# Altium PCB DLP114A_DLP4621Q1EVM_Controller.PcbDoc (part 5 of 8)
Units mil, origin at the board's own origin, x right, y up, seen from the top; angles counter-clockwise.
Board outline 4803.15 x 2598.43 mil, 14 copper layers (Top Layer, GND 1, SIGNAL 1, GND 2, SIGNAL 2, PWR SPLIT PLANE 1, GND 3, GND 4, PWR SPLIT PLANE 2, SIGNAL 3, GND 5, SIGNAL 4, GND 6, Bottom Layer), stack 91.4 mil thick; 489 components, 394 nets, 1925 pads, 1273 vias.
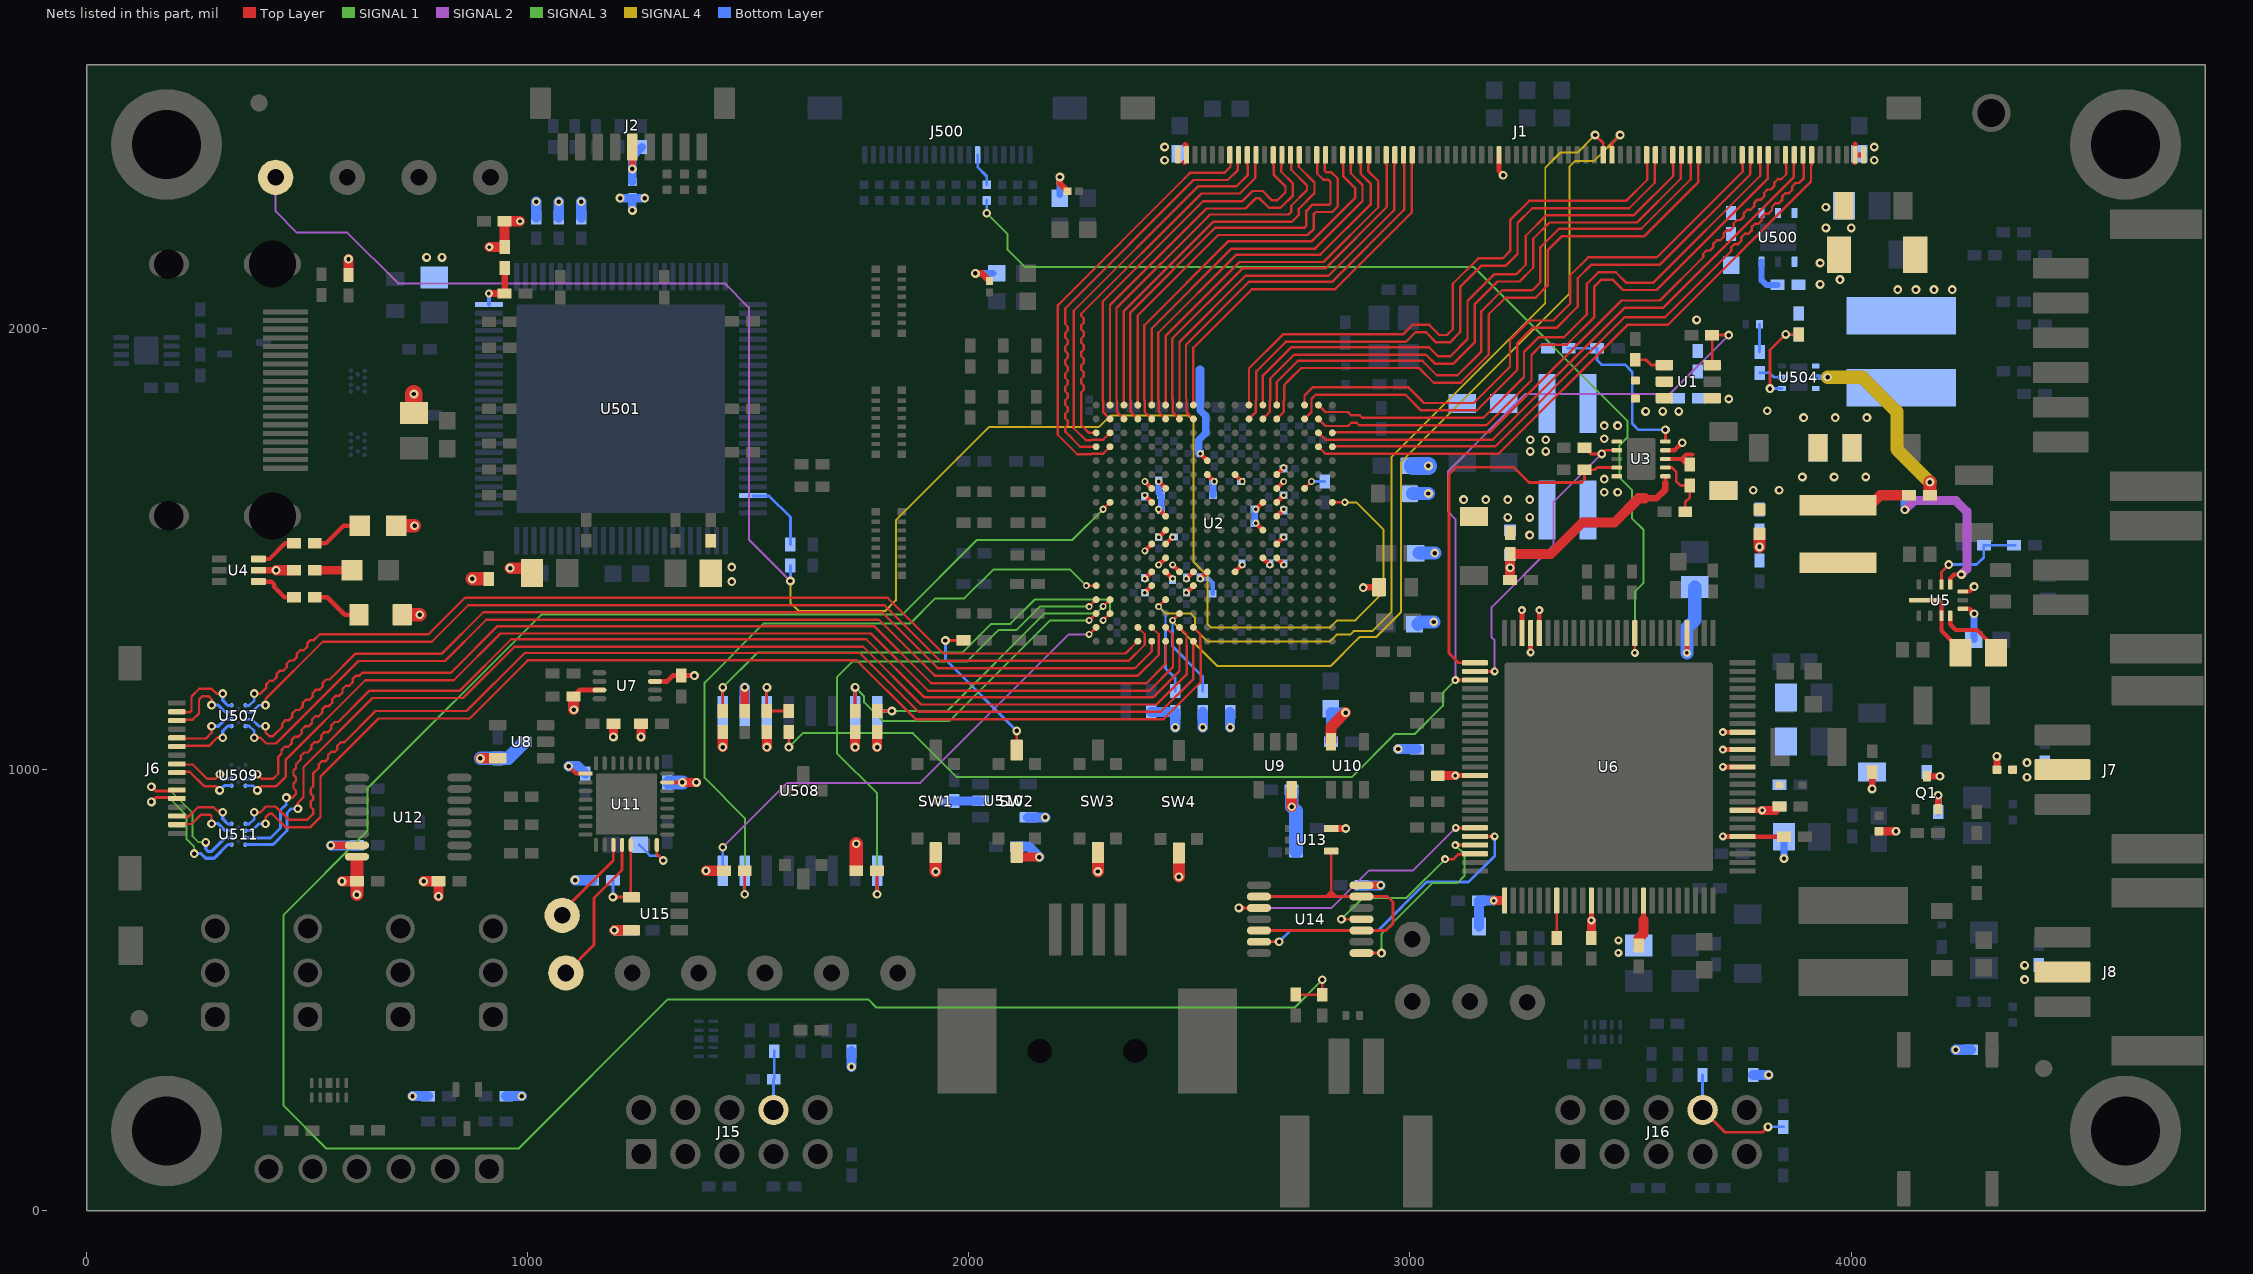
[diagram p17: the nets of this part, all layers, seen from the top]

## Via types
v1: diameter 20, hole 10, Top Layer to Bottom Layer, tented top, 716 vias
v2: diameter 16, hole 8, Top Layer to Bottom Layer, 234 vias
v3: diameter 19.68, hole 7.87, Top Layer to Bottom Layer, 170 vias
v4: diameter 18, hole 8, Top Layer to Bottom Layer, tented top, 78 vias
v5: diameter 18, hole 8, Top Layer to Bottom Layer, tented bottom, 51 vias
v6: diameter 39.37, hole 19.68, Top Layer to Bottom Layer, 24 vias

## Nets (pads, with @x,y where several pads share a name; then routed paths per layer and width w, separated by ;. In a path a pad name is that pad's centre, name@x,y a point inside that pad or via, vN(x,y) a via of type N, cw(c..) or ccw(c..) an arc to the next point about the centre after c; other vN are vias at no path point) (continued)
HS_A_WDATA1_N: J1.26 U2.A12 | length 1340.7
  Top Layer w5.4: U2.A12@2635.03,1826.6 2635.03,1910.14 2711.8,1986.91 2983.97,1986.91 3005.4,2008.35 3043.5,2008.35 3066.32,1985.53 3083.83,1985.53 3096.88,1998.58 3096.88,2101.45 3154.99,2159.57 3210.65,2159.57 3227.04,2175.96 3227.04,2246.25 3270.25,2289.46 3490.06,2289.46 3537.98,2337.37 3537.98,2369.87 3536.54,2371.32 J1.26@3536.54,2393.7
HS_A_WDATA1_P: J1.25 U2.B12 | length 1379.2
  Top Layer w5.4: U2.B12@2635.03,1795.11 2650.78,1810.86 2650.78,1836.47 2651.83,1837.52 2651.83,1903.18 2718.76,1970.11 2990.92,1970.11 3012.36,1991.55 3036.54,1991.55 3059.36,1968.73 3090.78,1968.73 3113.68,1991.63 3113.68,2094.49 3161.95,2142.77 3217.61,2142.77 3243.84,2169.01 3243.84,2239.29 3277.21,2272.66 3497.02,2272.66 3554.78,2330.41 3554.78,2369.87 3556.22,2371.32 J1.25@3556.22,2393.7
HS_A_WDATA2_N: J1.23 U2.A13 | length 1338.5
  Top Layer w5.4: U2.A13@2666.53,1826.6 2666.53,1893.63 2730.36,1957.46 3043.3,1957.46 3048.22,1952.54 3063.44,1937.32 3091.52,1937.32 3130.4,1976.2 3130.4,2062.38 3191.49,2123.46 3241.13,2123.46 3262.46,2144.79 3262.46,2210.53 3309.15,2257.22 3507.66,2257.22 3597.03,2346.59 3597.03,2369.87 3595.59,2371.32 J1.23@3595.59,2393.7
HS_A_WDATA2_P: J1.22 U2.B13 | length 1377
  Top Layer w5.4: U2.B13@2666.53,1795.11 2682.27,1810.86 2682.27,1836.47 2683.33,1837.52 2683.33,1886.67 2737.32,1940.66 3036.34,1940.66 3056.48,1920.52 3098.47,1920.52 3147.2,1969.25 3147.2,2055.42 3198.45,2106.66 3248.09,2106.66 3279.26,2137.83 3279.26,2203.57 3316.1,2240.42 3514.62,2240.42 3613.83,2339.63 3613.83,2369.87 3615.28,2371.32 J1.22@3615.28,2393.7
HS_A_WDATA3_N: J1.21 U2.A14 | length 1364.5
  Top Layer w5.4: U2.A14@2698.02,1826.6 2698.02,1878.84 2746.53,1927.35 3027.6,1927.35 3032.52,1922.43 3060.81,1894.15 3107.81,1894.15 3161.83,1948.16 3161.83,2039.37 3209.32,2086.86 3277.82,2086.86 3295.3,2104.34 3295.3,2183.97 3337.71,2226.38 3524.42,2226.38 3636.4,2338.37 3636.4,2369.87 3634.96,2371.32 J1.21@3634.96,2393.7
HS_A_WDATA3_P: J1.20 U2.B14 | length 1402.9
  Top Layer w5.4: U2.B14@2698.02,1795.11 2713.77,1810.86 2713.77,1836.47 2714.82,1837.52 2714.82,1871.88 2724.91,1881.97 2753.49,1910.55 3020.64,1910.55 3053.85,1877.35 3114.77,1877.35 3178.63,1941.2 3178.63,2032.41 3216.28,2070.06 3284.78,2070.06 3312.1,2097.38 3312.1,2177.01 3344.67,2209.58 3531.38,2209.58 3653.2,2331.41 3653.2,2369.87 3654.65,2371.32 J1.20@3654.65,2393.7
HS_A_WDATA4_N: J1.15 U2.A16 | length 1366.1
  Top Layer w5.4: U2.A16@2761.01,1826.6 2761.01,1848.67 2779.07,1866.72 2996.65,1866.72 3032.13,1831.24 3144.47,1831.24 3226.74,1913.51 3226.74,1973.93 3271.11,2018.3 3324.92,2018.3 3363.49,2056.87 3363.49,2120.95 3404.35,2161.81 3559.91,2161.81 3754.51,2356.42 3754.51,2369.87 3753.07,2371.32 J1.15@3753.07,2393.7
HS_A_WDATA4_P: J1.14 U2.B16 | length 1404.5
  Top Layer w5.4: U2.B16@2761.01,1795.11 2776.76,1810.86 2776.76,1840.66 2786.03,1849.92 2989.69,1849.92 3025.18,1814.44 3151.43,1814.44 3243.54,1906.55 3243.54,1966.98 3278.07,2001.5 3331.88,2001.5 3380.29,2049.91 3380.29,2113.99 3411.31,2145.01 3566.87,2145.01 3771.31,2349.46 3771.31,2369.87 3772.76,2371.32 J1.14@3772.76,2393.7
HS_A_WDATA5_N: J1.13 U2.A17 | length 1381.8
  Top Layer w5.4: U2.A17@2792.51,1826.6 2808.28,1810.83 2859.43,1810.83 2867.02,1803.24 2886.23,1803.24 2891.64,1797.83 3166.43,1797.83 3258.61,1890.01 3258.61,1947.12 3291.5,1980.01 3348.61,1980.01 3400.6,2032.01 3400.6,2101.22 3427.18,2127.8 3466.3,2127.8 3489.76,2104.34 3551.8,2104.34 3793.88,2346.42 3793.88,2369.87 3792.44,2371.32 J1.13@3792.44,2393.7
HS_A_WDATA5_P: J1.12 U2.B17 | length 1409.6
  Top Layer w5.4: U2.B17@2792.51,1795.11 2808.38,1779.24 2859.82,1779.24 2867.02,1786.44 2879.27,1786.44 2884.68,1781.03 3173.38,1781.03 3275.41,1883.05 3275.41,1940.16 3298.46,1963.21 3355.57,1963.21 3417.4,2025.05 3417.4,2094.26 3434.14,2111 3459.34,2111 3482.8,2087.54 3558.76,2087.54 3810.68,2339.46 3810.68,2369.87 3812.13,2371.32 J1.12@3812.13,2393.7
HS_A_WDATA6_N: J1.10 U2.C18 | length 1353.7
  Top Layer w5.4: U2.C18@2824.01,1763.61 2825.06,1764.66 3180.3,1764.66 3479.25,2063.62 3566.86,2063.62 3664.83,2161.58 3664.83,2169.57 3672.36,2177.1 3680.35,2177.1 3687.88,2184.63 3687.88,2192.62 3695.41,2200.15 3703.4,2200.15 3710.93,2207.69 3710.93,2215.68 3718.46,2223.21 3726.45,2223.21 3733.98,2230.74 3733.98,2238.73 3741.52,2246.26 3749.5,2246.26 3757.04,2253.79 3757.04,2261.78 3764.57,2269.31 3772.56,2269.31 3780.09,2276.84 3780.09,2284.83 3787.62,2292.36 3795.61,2292.36 3803.14,2299.9 3803.14,2307.88 3810.67,2315.42 3818.66,2315.42 3826.19,2322.95 3826.19,2330.94 3833.72,2338.47 3841.71,2338.47 3852.94,2349.69 3852.94,2369.87 3851.5,2371.32 J1.10@3851.5,2393.7
HS_A_WDATA6_P: J1.9 U2.C17 | length 1381.7
  Top Layer w5.4: U2.C17@2792.51,1763.61 2808.26,1747.86 3187.26,1747.86 3486.21,2046.82 3573.82,2046.82 3869.74,2342.74 3869.74,2369.87 3871.18,2371.32 J1.9@3871.18,2393.7
HS_A_WDATA7_N: J1.8 U2.D18 | length 1407.1
  Top Layer w5.4: U2.D18@2824.01,1732.12 2825.06,1733.17 3193.68,1733.17 3485.77,2025.26 3492.43,2025.26 3577.54,2025.26 3728.34,2176.06 3728.34,2184.05 3735.87,2191.58 3743.86,2191.58 3751.39,2199.12 3751.39,2207.1 3758.93,2214.64 3766.91,2214.64 3774.45,2222.17 3774.45,2230.16 3781.98,2237.69 3789.97,2237.69 3797.5,2245.22 3797.5,2253.21 3805.03,2260.74 3813.02,2260.74 3820.55,2268.27 3820.55,2276.26 3828.08,2283.79 3836.07,2283.79 3843.6,2291.33 3843.6,2299.31 3851.14,2306.85 3859.12,2306.85 3866.66,2314.38 3866.66,2322.37 3874.19,2329.9 3882.18,2329.9 3892.31,2340.03 3892.31,2369.87 3890.87,2371.32 J1.8@3890.87,2393.7
HS_A_WDATA7_P: J1.7 U2.D17 | length 1439.8
  Top Layer w5.4: U2.D17@2792.51,1732.12 2808.26,1716.37 3200.64,1716.37 3492.73,2008.46 3499.39,2008.46 3584.5,2008.46 3909.11,2333.07 3909.11,2369.87 3910.55,2371.32 J1.7@3910.55,2393.7
HS_B_CLK_N: J1.63 U2.A4 | length 915.2
  Top Layer w5.4: U2.A4@2383.06,1826.6 2383.06,2029.6 2565.51,2212.05 2767.99,2212.05 2782.06,2226.12 2782.06,2259.96 2786.33,2264.23 2823.66,2264.23 2836.67,2277.23 2836.67,2339.58 2822.12,2354.13 2810.55,2354.13 2806.75,2357.93 2806.75,2392.26 J1.63@2808.19,2393.7
HS_B_CLK_P: J1.64 U2.B4 | length 953.7
  Top Layer w5.4: U2.B4@2383.06,1795.11 2367.31,1810.86 2367.31,1836.06 2366.26,1837.11 2366.26,2036.55 2553.63,2223.93 2558.55,2228.85 2761.03,2228.85 2765.26,2233.08 2765.26,2266.92 2779.37,2281.03 2816.71,2281.03 2819.87,2284.19 2819.87,2332.62 2815.17,2337.33 2803.59,2337.33 2789.95,2350.97 2789.95,2392.26 J1.64@2788.5,2393.7
HS_B_WDATA0_N: J1.53 U2.A8 | length 883.1
  Top Layer w5.4: U2.A8@2509.05,1826.6 2509.05,1956.55 2641.61,2089.11 2830.28,2089.11 3003.6,2262.43 3003.6,2369.87 3005.04,2371.32 J1.53@3005.04,2393.7
HS_B_WDATA0_P: J1.54 U2.B8 | length 921.5
  Top Layer w5.4: U2.B8@2509.05,1795.11 2493.3,1810.86 2493.3,1840.97 2492.25,1842.03 2492.25,1963.5 2634.65,2105.91 2823.32,2105.91 2986.8,2269.39 2986.8,2369.87 2985.35,2371.32 J1.54@2985.35,2393.7
HS_B_WDATA1_N: J1.55 U2.A7 | length 879.4
  Top Layer w5.4: U2.A7@2477.55,1826.6 2477.55,1969.96 2627.35,2119.76 2815.31,2119.76 2964.23,2268.67 2964.23,2369.87 2965.67,2371.32 J1.55@2965.67,2393.7
HS_B_WDATA1_P: J1.56 U2.B7 | length 917.8
  Top Layer w5.4: U2.B7@2477.55,1795.11 2461.8,1810.86 2461.8,1840.66 2460.75,1841.71 2460.75,1976.92 2620.39,2136.56 2808.35,2136.56 2947.43,2275.63 2947.43,2369.87 2945.98,2371.32 J1.56@2945.98,2393.7
HS_B_WDATA2_N: J1.58 U2.A6 | length 888.3
  Top Layer w5.4: U2.A6@2446.05,1826.6 2446.05,1983.46 2613.44,2150.85 2803.71,2150.85 2928.1,2275.24 2928.1,2334.37 2905.17,2357.3 2905.17,2369.87 2906.61,2371.32 J1.58@2906.61,2393.7
HS_B_WDATA2_P: J1.59 U2.B6 | length 926.8
  Top Layer w5.4: U2.B6@2446.05,1795.11 2430.31,1810.86 2430.31,1836.47 2429.25,1837.52 2429.25,1990.42 2606.48,2167.65 2796.75,2167.65 2911.3,2282.2 2911.3,2327.41 2888.37,2350.35 2888.37,2369.87 2886.93,2371.32 J1.59@2886.93,2393.7
HS_B_WDATA3_N: J1.60 U2.A5 | length 887.6
  Top Layer w5.4: U2.A5@2414.56,1826.6 2414.56,2000.29 2595.66,2181.39 2784.89,2181.39 2892.49,2288.99 2892.49,2325.3 2865.8,2351.99 2865.8,2369.87 2867.24,2371.32 J1.60@2867.24,2393.7
HS_B_WDATA3_P: J1.61 U2.B5 | length 926
  Top Layer w5.4: U2.B5@2414.56,1795.11 2398.81,1810.86 2398.81,1836.06 2397.76,1837.11 2397.76,2007.25 2588.7,2198.19 2777.93,2198.19 2875.69,2295.95 2875.69,2318.34 2849,2345.03 2849,2369.87 2847.56,2371.32 J1.61@2847.56,2393.7
HS_B_WDATA4_N: J1.66 U2.A3 | length 865.7
  Top Layer w5.4: U2.A3@2351.57,1826.6 2351.57,2039.53 2553.81,2241.78 2731.86,2241.78 2747.69,2257.62 2747.69,2271.38 2783.45,2307.14 2783.45,2331.18 2747.69,2366.94 2747.69,2392.26 J1.66@2749.13,2393.7
HS_B_WDATA4_P: J1.67 U2.B3 | length 904.1
  Top Layer w5.4: U2.B3@2351.57,1795.11 2335.82,1810.86 2335.82,1836.06 2334.77,1837.11 2334.77,2046.49 2541.93,2253.66 2546.85,2258.58 2724.9,2258.58 2730.89,2264.58 2730.89,2278.34 2766.65,2314.1 2766.65,2324.22 2730.89,2359.98 2730.89,2392.26 J1.67@2729.45,2393.7
HS_B_WDATA5_N: J1.68 U2.A2 | length 865.2
  Top Layer w5.4: U2.A2@2320.07,1826.6 2320.07,2053.8 2538.36,2272.09 2627.09,2272.09 2650.1,2295.11 2659.14,2295.11 2680.5,2273.76 2706.2,2273.76 2734.5,2302.06 2734.5,2329.2 2708.32,2355.38 2708.32,2369.87 2709.76,2371.32 J1.68@2709.76,2393.7
HS_B_WDATA5_P: J1.69 U2.B2 | length 903.7
  Top Layer w5.4: U2.B2@2320.07,1795.11 2304.32,1810.86 2304.32,1836.06 2303.27,1837.11 2303.27,2060.76 2531.4,2288.89 2620.13,2288.89 2643.15,2311.91 2666.1,2311.91 2687.46,2290.56 2699.24,2290.56 2717.7,2309.02 2717.7,2322.24 2691.52,2348.42 2691.52,2369.87 2690.08,2371.32 J1.69@2690.08,2393.7
HS_B_WDATA6_N: J1.71 U2.C1 | length 898.3
  Top Layer w5.4: U2.C1@2288.57,1763.61 2272.31,1763.61 2254.75,1781.18 2254.75,1855.69 2260.75,1861.69 2260.75,1870.29 2254.75,1876.29 2254.75,1886.18 2260.75,1892.18 2260.75,1900.78 2254.75,1906.78 2254.75,1916.66 2260.75,1922.66 2260.75,1931.26 2254.75,1937.26 2254.75,1947.15 2260.75,1953.15 2260.75,1961.75 2254.75,1967.75 2254.75,1977.64 2260.75,1983.64 2260.75,1992.23 2254.75,1998.23 2254.75,2008.12 2260.75,2014.12 2260.75,2022.72 2254.75,2028.72 2254.75,2033.58 2527.46,2306.29 2614.24,2306.29 2649.27,2341.31 2649.27,2369.87 2650.71,2371.32 J1.71@2650.71,2393.7
HS_B_WDATA6_P: J1.72 U2.C2 | length 934.8
  Top Layer w5.4: U2.C2@2320.07,1763.61 2304.32,1747.86 2279.12,1747.86 2278.07,1746.81 2265.35,1746.81 2237.95,1774.22 2237.95,1881.97 2237.95,2040.54 2520.5,2323.09 2607.28,2323.09 2632.47,2348.27 2632.47,2369.87 2631.02,2371.32 J1.72@2631.02,2393.7
HS_B_WDATA7_N: J1.73 U2.D1 | length 959.6
  Top Layer w5.4: U2.D1@2288.57,1732.12 2252.67,1732.12 2218.34,1766.45 2218.34,1776.34 2224.34,1782.34 2224.34,1790.94 2218.34,1796.94 2218.34,1806.83 2224.34,1812.83 2224.34,1821.42 2218.34,1827.42 2218.34,1837.31 2224.34,1843.31 2224.34,1851.91 2218.34,1857.91 2218.34,1867.8 2224.34,1873.8 2224.34,1882.39 2218.34,1888.39 2218.34,1898.28 2224.34,1904.28 2224.34,1912.88 2218.34,1918.88 2218.34,1928.77 2224.34,1934.77 2224.34,1943.37 2218.34,1949.37 2218.34,1959.25 2224.34,1965.25 2224.34,1973.85 2218.34,1979.85 2218.34,1989.74 2224.34,1995.74 2224.34,2004.34 2218.34,2010.34 2218.34,2045.72 2509.52,2336.89 2586.96,2336.89 2609.9,2359.83 2609.9,2392.26 J1.73@2611.34,2393.7
HS_B_WDATA7_P: J1.74 U2.D2 | length 986.1
  Top Layer w5.4: U2.D2@2320.07,1732.12 2304.32,1716.37 2279.12,1716.37 2278.07,1715.32 2245.72,1715.32 2201.54,1759.49 2201.54,2052.68 2490.68,2341.81 2502.56,2353.69 2580,2353.69 2593.1,2366.79 2593.1,2392.26 J1.74@2591.65,2393.7
HSEL_PU: R37.2 SW2.1 | length 356.4
  Top Layer w6.3: v1(1946.79,1293.01) R37.2@1987.78,1293.01 ; SW2.1@2108.66,1044.67 v1(2108.66,1088.07)
  Bottom Layer w6.3: v1(1946.79,1293.01) 1946.79,1249.94 v1(2108.66,1088.07)
HSYNC: R539.2 TP1.1 U2.H18 | length 4392.7
  Top Layer w6.3: U2.H18@2824.13,1606.26 v2(2852.49,1606.26)
  SIGNAL 4 w4.5: v1(1595.45,1427.84) 1595.45,1378.39 1614.09,1359.75 1810.45,1359.75 1834.39,1383.69 1834.39,1565.36 2046.22,1777.18 2295.41,1777.18 2321.21,1802.98 2497.12,1802.98 2509.23,1790.88 2509.23,1471.48 2540.59,1440.13 2540.59,1330.56 2548.5,1322.64 2819.5,1322.64 2835.35,1338.5 2876.09,1338.5 2939.78,1402.2 2939.78,1544.89 2878.41,1606.26 v2(2852.49,1606.26)
  SIGNAL 2 w4.5: TP1.1@428.53,2342.8 428.53,2265.59 476.47,2217.65 590.92,2217.65 705.98,2102.58 1446.35,2102.58 1501.38,2047.56 1501.38,1521.9 v1(1595.45,1427.84)
  Bottom Layer w6.3: v1(1595.45,1427.84) R539.2@1595.45,1463.04
HSYNC_S: R539.1 U501.48 | length 167.5
  Bottom Layer w6.3: U501.48@1510.53,1621.47 1511.23,1620.77 1547.3,1620.77 1595.45,1572.62 R539.1@1595.45,1510.28
HUD_LEDSEL_0: U6.20 U14.3 | length 655.7
  Top Layer w6.3: v1(2612.12,686.71) U14.3@2657.68,686.71 ; v4(3103.78,868.12) U6.20@3147.12,868.12
  SIGNAL 2 w4.5: v1(2612.12,686.71) 2822.17,686.71 2907.22,771.76 3007.43,771.76 v4(3103.78,868.12)
HUD_LEDSEL_1: U6.21 U14.6 | length 703.7
  Top Layer w6.3: U14.6@2657.68,609.94 v1(2703.24,609.94) ; U6.21@3147.52,848.84 v4(3192.05,848.84)
  Bottom Layer w6.3: v1(2703.24,609.94) 2729.17,635.87 2928.18,635.87 3037.86,745.55 3132.85,745.55 3192.05,804.74 v4(3192.05,848.84)
HUD_LEDSEL_2: U6.22 U14.8 | length 454.6
  Top Layer w6.3: U14.8@2889.97,584.35 v1(2935.52,584.35) ; v4(3103,829.15) U6.22@3147.52,829.15
  SIGNAL 3 w4.5: v1(2935.52,584.35) 2935.52,628.02 3050.36,742.86 3107.18,742.86 3123.63,759.32 3123.63,808.51 v4(3103,829.15)
HUD_LEDSEL_3: U6.23 U14.11 | length 410.1
  Top Layer w6.3: v1(2844.41,661.12) U14.11@2889.97,661.12 ; v4(3079.8,797.19) 3099,797.19 3110.37,808.56 3146.62,808.56 U6.23@3147.52,809.47
  SIGNAL 3 w4.5: v1(2844.41,661.12) 2892.43,709.15 2991.76,709.15 v4(3079.8,797.19)
JTAGRSTZ: R531.2 U2.G16 | length 52.1
  Top Layer w6.3: U2.G16@2761.01,1637.63 v2(2776.76,1653.38)
  Bottom Layer w6.3: v2(2776.76,1653.38) R531.2@2806.57,1653.38
L1_CLK_N: U2.U6 U509.C4 | length 2449.9
  Top Layer w5.4: v1(387.28,953.13) 397.08,962.92 430.38,962.92 451.19,983.73 451.19,1022.21 631.73,1202.74 832.31,1202.74 938.37,1308.8 1778.09,1308.8 1907.79,1179.11 2409.35,1179.11 2462.85,1232.62 2462.85,1280.7 2461.8,1281.75 2461.8,1306.92 U2.U6@2446.05,1322.67
  Bottom Layer w6.3: U509.C4@360.17,963.82 376.59,963.82 v1(387.28,953.13)
L1_CLK_N_S: J6.9 U509.A4 | length 146.3
  Top Layer w5.4: J6.9@204.72,993.51 206.17,994.96 233.85,994.96 266.08,962.73 291.96,962.73 v1(301.56,953.13)
  Bottom Layer w7: v1(301.56,953.13) 312.25,963.82 U509.A4@328.67,963.82
L1_CLK_P: U2.V6 U509.C3 | length 2421
  Top Layer w5.4: v1(386.78,989.51) 396.57,979.72 423.42,979.72 434.39,990.69 434.39,1029.17 441.73,1036.51 441.73,1044.5 449.27,1052.03 457.25,1052.03 464.79,1059.56 464.79,1067.55 472.32,1075.08 480.31,1075.08 487.84,1082.61 487.84,1090.6 495.37,1098.13 503.36,1098.13 510.89,1105.67 510.89,1113.65 518.42,1121.19 526.41,1121.19 533.94,1128.72 533.94,1136.71 541.47,1144.24 549.46,1144.24 557,1151.77 557,1159.76 564.53,1167.29 572.52,1167.29 580.05,1174.82 580.05,1182.81 587.58,1190.34 595.57,1190.34 603.1,1197.88 603.1,1205.86 610.63,1213.4 618.62,1213.4 624.77,1219.54 825.35,1219.54 931.41,1325.6 1785.05,1325.6 1914.75,1195.91 2402.39,1195.91 2446.05,1239.57 U2.V6@2446.05,1291.17
  Bottom Layer w6.3: U509.C3@360.17,978.82 376.09,978.82 v1(386.78,989.51)
L1_CLK_P_S: J6.8 U509.A3 | length 146.5
  Top Layer w5.4: J6.8@204.72,1013.2 206.17,1011.76 240.81,1011.76 273.04,979.53 292.08,979.53 v1(302.06,989.51)
  Bottom Layer w7: v1(302.06,989.51) 312.75,978.82 U509.A3@328.67,978.82
L1_DATA0_N: U2.U4 U507.C2 | length 2260.5
  Top Layer w5.4: v1(405.54,1146.34) 405.54,1160.19 535.46,1290.11 782.26,1290.11 865,1372.84 1808.95,1372.84 1935.18,1246.6 2362.25,1246.6 2398.81,1283.16 2398.81,1306.92 U2.U4@2383.06,1322.67
  Bottom Layer w6.3: U507.C2@360.17,1130.69 374.77,1130.69 390.42,1146.34 v1(405.54,1146.34)
L1_DATA0_N_S: J6.3 U507.A2 | length 188.3
  Top Layer w5.4: J6.3@204.72,1111.62 206.17,1113.07 240.28,1113.07 254.68,1127.47 254.68,1159.29 262.26,1166.87 276.21,1166.87 283.3,1159.78 v1(283.3,1146.34)
  Bottom Layer w7: v1(283.3,1146.34) 298.42,1146.34 314.07,1130.69 U507.A2@328.67,1130.69
L1_DATA0_P: U2.V4 U507.C1 | length 2220
  Top Layer w5.4: v1(380.17,1172.43) 394.02,1172.43 407.64,1186.05 407.64,1194.04 415.17,1201.57 423.16,1201.57 430.69,1209.1 430.69,1217.09 438.22,1224.62 446.21,1224.62 453.74,1232.15 453.74,1240.14 461.27,1247.67 469.26,1247.67 476.79,1255.2 476.79,1263.19 484.33,1270.72 492.31,1270.72 499.85,1278.26 499.85,1286.25 507.38,1293.78 515.37,1293.78 528.5,1306.91 775.3,1306.91 858.04,1389.64 1815.9,1389.64 1942.14,1263.4 2355.29,1263.4 U2.V4@2383.06,1291.17
  Bottom Layer w6.3: U507.C1@360.17,1145.69 368.56,1145.69 380.17,1157.31 v1(380.17,1172.43)
L1_DATA0_P_S: J6.2 U507.A1 | length 190.1
  Top Layer w5.4: J6.2@204.72,1131.31 206.17,1129.87 233.32,1129.87 237.88,1134.43 237.88,1166.25 255.31,1183.67 283.17,1183.67 294.41,1172.43 v1(308.67,1172.43)
  Bottom Layer w7: v1(308.67,1172.43) 308.67,1157.31 320.28,1145.69 U507.A1@328.67,1145.69
L1_DATA1_N: U2.U5 U507.C4 | length 2352.7
  Top Layer w5.4: v1(380.17,1072.46) 394.02,1072.46 407.19,1059.3 429.63,1059.3 616.72,1246.38 812.26,1246.38 905.94,1340.06 1795.98,1340.06 1922.78,1213.26 2383.25,1213.26 2430.31,1260.32 2430.31,1306.92 U2.U5@2414.56,1322.67
  Bottom Layer w6.3: U507.C4@360.17,1099.2 368.56,1099.2 380.17,1087.58 v1(380.17,1072.46)
L1_DATA1_N_S: J6.6 U507.A4 | length 152.1
  Top Layer w5.4: J6.6@204.72,1052.57 206.17,1054.01 277.38,1054.01 295.84,1072.46 v1(308.67,1072.46)
  Bottom Layer w7: v1(308.67,1072.46) 308.67,1087.58 320.28,1099.2 U507.A4@328.67,1099.2
L1_DATA1_P: U2.V5 U507.C3 | length 2309.2
  Top Layer w5.4: v1(405.54,1098.55) 405.54,1084.7 414.14,1076.1 422.68,1076.1 443.46,1096.88 443.46,1104.87 450.99,1112.4 458.98,1112.4 466.51,1119.93 466.51,1127.92 474.05,1135.45 482.04,1135.45 489.57,1142.99 489.57,1150.98 497.1,1158.51 505.09,1158.51 512.62,1166.04 512.62,1174.03 520.15,1181.56 528.14,1181.56 535.67,1189.09 535.67,1197.08 543.2,1204.61 551.19,1204.61 609.76,1263.18 805.3,1263.18 898.98,1356.86 1802.94,1356.86 1929.74,1230.06 2376.29,1230.06 2414.56,1268.33 U2.V5@2414.56,1291.17
  Bottom Layer w6.3: U507.C3@360.17,1114.2 374.77,1114.2 390.42,1098.55 v1(405.54,1098.55)
L1_DATA1_P_S: J6.5 U507.A3 | length 151.2
  Top Layer w5.4: J6.5@204.72,1072.25 206.17,1070.81 270.42,1070.81 283.3,1083.69 v1(283.3,1098.55)
  Bottom Layer w7: v1(283.3,1098.55) 298.42,1098.55 314.07,1114.2 U507.A3@328.67,1114.2
L1_DATA2_N: U2.U7 U511.C4 | length 2587
  Top Layer w5.4: v1(478.89,911.4) 478.89,925.25 491.58,937.93 491.58,1005.54 648.46,1162.43 853.33,1162.43 969.71,1278.8 1760.5,1278.8 1891.53,1147.77 2425.5,1147.77 2494.35,1216.62 2494.35,1280.7 2493.3,1281.75 2493.3,1306.92 U2.U7@2477.55,1322.67
  Bottom Layer w6.3: U511.C4@360.17,830.47 423.2,830.47 454.52,861.79 454.52,902.14 463.77,911.4 v1(478.89,911.4)
L1_DATA2_N_S: J6.12 U511.A4 | length 359.5
  Top Layer w7: v1(146.99,927.08) 156.71,936.8 202.38,936.8 J6.12@204.72,934.46
  SIGNAL 1 w4: v1(146.99,927.08) 158.27,938.36 184.44,938.36 226.16,896.64 226.16,843.07 244.01,825.23 v1(244.01,809.95)
  Bottom Layer w7: v1(244.01,809.95) 259.13,809.95 ; 259.49,809.59 269.88,799.2 289.01,799.2 320.28,830.47 U511.A4@328.67,830.47
L1_DATA2_P: U2.V7 U511.C3 | length 2550.3
  Top Layer w5.4: v1(452.8,936.77) 466.65,936.77 474.78,944.89 474.78,952.31 469.13,957.96 469.13,968.61 474.78,974.26 474.78,982.26 469.13,987.91 469.13,998.56 474.78,1004.21 474.78,1012.5 485.84,1023.57 485.84,1031.55 493.37,1039.09 501.36,1039.09 508.89,1046.62 508.89,1054.61 516.43,1062.14 524.41,1062.14 531.95,1069.67 531.95,1077.66 539.48,1085.19 547.47,1085.19 555,1092.72 555,1100.71 562.53,1108.24 570.52,1108.24 641.51,1179.23 846.37,1179.23 962.75,1295.6 1767.46,1295.6 1898.49,1164.57 2418.55,1164.57 2477.55,1223.58 U2.V7@2477.55,1291.17
  Bottom Layer w6.3: U511.C3@360.17,845.47 416.99,845.47 439.52,868 439.52,908.36 452.8,921.65 v1(452.8,936.77)
L1_DATA2_P_S: J6.11 U511.A3 | length 358.6
  Top Layer w7: v1(146.99,961.52) 156.71,951.8 202.38,951.8 J6.11@204.72,954.14
  SIGNAL 1 w4: v1(146.99,961.52) 156.15,952.36 190.24,952.36 240.16,902.44 240.16,848.87 253.71,835.32 v1(270.09,835.32)
  Bottom Layer w7: v1(270.09,835.32) 270.09,820.2 276.1,814.2 282.79,814.2 314.07,845.47 U511.A3@328.67,845.47
L1_DATA3_N: U2.U8 U511.C2 | length 2632.9
  Top Layer w5.4: v1(405.54,877.62) 405.54,891.47 413.83,899.75 420.97,899.75 450.77,869.96 507.71,869.96 530.36,892.6 530.36,984.57 661.98,1116.2 868.44,1116.2 1000.06,1247.83 1745.84,1247.83 1878.93,1114.74 2441.72,1114.74 2525.85,1198.86 2525.85,1280.7 2524.79,1281.75 2524.79,1306.92 U2.U8@2509.05,1322.67
  Bottom Layer w6.3: U511.C2@360.17,861.97 374.77,861.97 390.42,877.62 v1(405.54,877.62)
L1_DATA3_N_S: J6.15 U511.A2 | length 158.6
  Top Layer w5.4: J6.15@204.72,875.4 206.17,876.85 238.18,876.85 259.55,898.21 280.05,898.21 283.21,895.05 283.21,877.71 v1(283.3,877.62)
  Bottom Layer w7: v1(283.3,877.62) 298.42,877.62 314.07,861.97 U511.A2@328.67,861.97
L1_DATA3_P: U2.V8 U511.C1 | length 2591.5
  Top Layer w5.4: v1(380.17,903.7) 394.02,903.7 406.87,916.55 427.93,916.55 457.73,886.76 500.76,886.76 513.56,899.56 513.56,910.4 507.91,916.05 507.91,926.7 513.56,932.35 513.56,940.35 507.91,946 507.91,956.65 513.56,962.3 513.56,991.53 526.09,1004.06 526.09,1012.05 533.62,1019.58 541.61,1019.58 547.27,1025.24 547.27,1033.23 554.8,1040.76 562.79,1040.76 568.45,1046.42 568.45,1054.41 575.98,1061.94 583.97,1061.94 655.02,1133 861.48,1133 993.11,1264.63 1752.8,1264.63 1885.88,1131.54 2434.76,1131.54 2509.05,1205.82 U2.V8@2509.05,1291.17
  Bottom Layer w6.3: U511.C1@360.17,876.97 368.56,876.97 380.17,888.58 v1(380.17,903.7)
L1_DATA3_P_S: J6.14 U511.A1 | length 158
  Top Layer w5.4: J6.14@204.72,895.09 206.17,893.65 231.22,893.65 252.59,915.01 287.66,915.01 295.79,906.88 305.49,906.88 v1(308.67,903.7)
  Bottom Layer w7: v1(308.67,903.7) 308.67,888.58 320.28,876.97 U511.A1@328.67,876.97
LED_ANODE_DIVIDED: L503.1 U6.85 | length 2306.1
  Top Layer w6.3: v4(3509.73,1264.94) U6.85@3509.73,1309.47
  SIGNAL 3 w4.5: v1(2040.63,2261.61) 2087.89,2214.35 2087.89,2178.67 2126.83,2139.73 3144,2139.73 3493.62,1790.11 3493.62,1754.19 3475.23,1735.8 3475.23,1661.92 3502.87,1634.28 3502.87,1570.18 3529.63,1543.42 3529.63,1423.54 3509.73,1403.64 v4(3509.73,1264.94)
  Bottom Layer w6.3: v1(2040.63,2261.61) L503.1@2040.63,2290.45
LED_ANODE_DIVIDED_F: J500.14 L503.2 | length 76.4
  Bottom Layer w6.3: J500.14@2019.99,2393.7 2019.99,2365.94 2040.63,2345.3 L503.2@2040.63,2325.88
MSTR_SCL: J1.31 R554.2 U2.R6 | length 2180.8
  Top Layer w6.3: v2(2430.31,1369.91) U2.R6@2446.05,1385.66 ; v1(3419.67,2438.93) 3438.1,2420.49 J1.31@3438.11,2393.7
  SIGNAL 4 w4.5: v2(2430.31,1369.91) 2445.72,1354.5 2502.61,1354.5 2512.36,1344.74 2512.36,1319.67 2541.85,1290.19 2817.67,1290.19 2833.9,1306.42 2864.18,1306.42 2872.12,1314.36 2914.76,1314.36 2958.64,1358.24 2958.64,1709.11 3306.64,2057.11 3306.64,2364.67 3341.17,2399.2 3379.94,2399.2 v1(3419.67,2438.93)
  Bottom Layer w5: v2(2430.31,1369.91) 2446.01,1354.21 2446.01,1325.1
  Bottom Layer w6.3: 2446.01,1325.1 2446.01,1229.87 2467.76,1208.12 R554.2@2467.76,1178.31
MSTR_SDA: J1.30 R558.2 U2.T7 | length 2188.6
  Top Layer w6.3: v2(2461.8,1338.42) U2.T7@2477.55,1354.16 ; J1.30@3457.8,2393.7 3457.8,2420.48 v1(3476.23,2438.92)
  SIGNAL 4 w4.5: v2@2460.01,1337.71 2561.48,1236.24 2562.41,1235.31 2820.23,1235.31 2821.16,1236.24 2879.39,1294.47 2885.73,1300.8 2923.69,1300.8 2979.23,1356.34 2979.23,1696.75 3361.45,2078.97 3361.45,2366.83 3374.58,2379.96 3417.28,2379.96 v1@3476.11,2438.8
  Bottom Layer w5: 2461.8,1317.26 v2(2461.8,1338.42)
  Bottom Layer w6.3: 2461.8,1317.26 2461.8,1279.94 2530.07,1211.67 R558.2@2530.07,1178.31
N8_FET_S: Q1.2 R566.1 | length 70
  Top Layer w15: Q1.2@4197.29,910.37 v1(4197.29,942.12)
  Bottom Layer w15: R566.1@4197.29,903.86 v1(4197.29,942.12)
N8V: C46.1 C591.1 L6.1 Q1.3 R562.2 U6.63 | length 140
  Top Layer w11.8: v4(3709.3,1006.32) U6.63@3753.82,1006.32
  Top Layer w15: v1@4047.58,958.51 C46.1@4047.58,994.5 ; Q1.3@4171.7,985.18 v1(4201.25,985.18) ; L6.1@4330.63,1000.23 v1(4330.63,1030.2)
  other v1: 4047.58,956.51
N8V_FIL: C594.1 C617.1 J7.2 J8.2 L6.2
  other v1: 4393.42,524.26 4393.42,556.37 4398.72,982.91 4398.72,1015.99
NetC12_1: C12.1 U1.4 | length 71.2
  Top Layer w6.3: C12.1@3510.7,1929.45 3534.59,1929.45 3546.85,1917.19 U1.4@3576.81,1917.19
NetC26_1: C26.1 R535.1 R544.2 U5.7 | length 59.9
  Top Layer w9.84: U5.7@4253.1,1404.04 4267.61,1404.04 v1(4278.72,1415.14)
  Top Layer w27: v1(3792.3,1505.04) C26.1@3792.3,1534.76
NetC38_1: C38.1 L2.1 U5.3 U5.12 | length 171.1
  Top Layer w9.84: U5.12@4166.96,1384.35 4197.83,1384.35 4204.87,1377.31 U5.3@4204.87,1348.92 4204.87,1314.81 4248.18,1271.51 C38.1@4248.18,1265.01
NetC38_2: C38.2 U5.4 | length 155.2
  Top Layer w9.84: U5.4@4224.56,1348.92 4224.56,1329.54 4237.22,1316.87 4285.66,1316.87 4328.18,1274.36 C38.2@4328.18,1265.01
NetC48_1: C48.1 D5.1 R563.1 R565.2 U6.58 | length 87.6
  Top Layer w11.8: U6.58@3753.82,907.89 v4(3798.35,907.89) ; C48.1@3829.1,907.89 C48.1@3837.79,916.58
  Top Layer w20: v4(3798.35,907.89) C48.1@3829.1,907.89
NetC519_2: C519.2 R517.1 | length 63.1
  Bottom Layer w6.3: R517.1@3792.63,1946.91 C519.2@3792.63,2010.04
NetC561_1: C561.1 R24.1 R32.2 U3.1 | length 531
  Top Layer w9: 3579.11,1650.22 U3.1@3579.11,1665.12
  Top Layer w15: 3533.12,1615.33 3559.12,1615.33 3579.11,1635.32 3579.11,1650.22
  Top Layer w23: R24.1@3226.95,1489.12 3319.67,1489.12 3391.13,1560.58 3463.56,1560.58 3518.31,1615.33 3533.12,1615.33 ; R32.2@3226.99,1430.18 R24.1@3226.95,1489.12
  Bottom Layer w23: v1(3226.95,1457.66) C561.1@3226.95,1487.25
NetC587_1: C587.1 U5.5 | length 88.8
  Top Layer w9.84: U5.5@4253.1,1364.67 4267.61,1364.67 v1(4278.72,1353.56)
  Bottom Layer w15: C587.1@4278.72,1295.01 v1(4278.72,1353.56)
NetC605_1: C605.1 U11.16 | length 109.8
  Top Layer w6.3: U11.16@1292.38,829.5 1292.38,808.98 v1@1307.11,794.25
  Bottom Layer w6.3: C605.1@1253.01,829.5 1277.38,805.13 1296.01,805.13 v1@1306.89,794.25
  other v1: 1307.34,794.25
NetC618_1: C618.1 J15.8 R583.1 | length 133.6
  Bottom Layer w6.3: J15.8@1557.29,228.74 C618.1@1557.29,298.08 ; C618.1@1557.77,298.56 1558.9,299.69 R583.1@1558.9,362.37
NetC619_1: C619.1 J16.8 R589.1 | length 288.4
  Top Layer w6.3: J16.8@3663.48,228.74 3713.98,178.24 3799.37,178.24 v1(3811.53,190.4)
  Bottom Layer w6.3: R589.1@3663.34,308.03 3663.34,228.88 J16.8@3663.48,228.74 ; v1(3811.53,190.4) C619.1@3846.59,190.4
NetD1_2: D1.2 L516.2 U504.4
  other v1: 4105.59,2088.38 4146.78,2088.38 4187.96,2088.38 4229.14,2088.38
NetD2_2: D2.2 R25.1 | length 118.5
  Top Layer w10: R25.1@517.18,1513.12 542.5,1513.12 582.5,1553.12 D2.2@619.11,1553.12
NetD3_1: D3.1 R31.1 | length 84.3
  Top Layer w20: R31.1@517.18,1452.12 D3.1@601.46,1452.12
NetD4_1: D4.1 R34.1 | length 116.6
  Top Layer w10: R34.1@517.18,1391.12 545.27,1391.12 585.27,1351.12 D4.1@617.18,1351.12
NetL518_1: L518.1 U3.6
  other v1: 3440.56,1750.18 3440.56,1780.18 3470.56,1780.18
NetL520_1: L520.1 U3.10
  other v1: 3440.56,1628.81 3470.56,1628.81 3440.56,1658.81
NetR4_2: R4.2 R508.1 U504.1 | length 224
  Top Layer w6.3: v1(3816.23,1864.07) 3816.23,1951.49 v1(3851.66,1986.92) R4.2@3881.47,1986.92
  Bottom Layer w6.3: v1(3816.23,1864.07) U504.1@3843.08,1864.07 ; v1(3851.66,1986.92) R508.1@3881.47,1986.92
NetR9_1: R9.1 U1.5
NetR14_1: R14.1 R21.2 U3.2 | length 148.6
  Top Layer w6.3: U3.2@3579.11,1684.81 3594.22,1684.81 3603.84,1675.19 3603.84,1653.65 3613.02,1644.48 R14.1@3634.38,1644.48 3634.38,1617.39 3624.12,1607.13 R21.2@3624.12,1584.74
NetR25_2: R25.2 U4.6 | length 95.1
  Top Layer w10: U4.6@389.46,1477.73 414.6,1477.73 449.98,1513.12 R25.2@469.93,1513.12
NetR34_2: R34.2 U4.4 | length 98.3
  Top Layer w10: U4.4@389.46,1426.55 418.45,1426.55 425.38,1419.62 425.38,1414.22 448.47,1391.12 R34.2@469.93,1391.12
NetR42_1: R42.1 U2.T1 U508.7 | length 793.7
  Top Layer w6.3: R42.1@1742.05,1133.14 v1(1742.05,1186.58) ; v2(2272.83,1338.42) U2.T1@2288.57,1354.16
  SIGNAL 3 w4.5: v1(1742.05,1186.58) 1762.67,1165.96 1762.67,1152.53 1804.67,1110.54 1956.5,1110.54 2184.38,1338.42 v2(2272.83,1338.42)
  Bottom Layer w6.3: U508.7@1742.05,1133.14 v1(1742.05,1186.58)
NetR43_1: R43.1 U2.R2 U508.8 | length 665.9
  Top Layer w6.3: R43.1@1792.05,1133.14 v1(1825.5,1133.14) ; v2@2304.41,1370.08 U2.R2@2319.99,1385.66
  SIGNAL 3 w4.5: v1(1825.5,1133.14) 1950.57,1133.14 2171.64,1354.21 2288.45,1354.21 v2(2304.32,1370.08)
  Bottom Layer w6.3: U508.8@1792.05,1133.14 v1(1825.5,1133.14)
NetR44_1: R44.1 U2.T2 U508.1 | length 1137.6
  Top Layer w6.3: R44.1@1442.05,1133.14 v1(1442.05,1186.58) ; v2@2304.37,1338.68 U2.T2@2319.85,1354.16
  SIGNAL 3 w4.5: v1(1442.05,1186.58) 1520.84,1265.37 1985.16,1265.37 2050.61,1330.82 2094,1330.82 2149.02,1385.83 2310.77,1385.83 2320.02,1376.58 2320.02,1354.55 v2@2304.15,1338.68
  Bottom Layer w6.3: U508.1@1442.05,1133.14 v1(1442.05,1186.58)
  other v2: 2304.15,1338.42
NetR45_1: R45.1 R46.1 U508.3 | length 156.9
  Top Layer w6.3: v1(1542.05,1186.58) R45.1@1542.05,1133.14 R46.1@1592.05,1133.14
  Bottom Layer w6.3: U508.3@1542.05,1133.14 v1(1542.05,1186.58)
NetR58_1: R58.1 U2.R1 U508.9 | length 1297.3
  Top Layer w6.3: v1(1792.05,717.48) R58.1@1792.05,770.93 ; v2(2272.83,1369.91) U2.R1@2288.57,1385.66
  SIGNAL 3 w4.5: v1(1792.05,717.48) 1792.05,946.62 1700.97,1037.7 1700.97,1209.61 1736.98,1245.62 1995.86,1245.62 2066.7,1316.47 2107.7,1316.47 2161.14,1369.91 v2(2272.83,1369.91)
  Bottom Layer w6.3: v1(1792.05,717.48) U508.9@1792.05,770.93
NetR59_1: R59.1 U2.P1 U508.15 | length 1634.1
  Top Layer w6.3: v1(1492.05,717.48) R59.1@1492.05,770.93 ; v2(2266.3,1417.16) U2.P1@2288.57,1417.16
  SIGNAL 3 w4.5: v1(1492.05,717.48) 1492.05,890.4 1400.8,981.65 1400.8,1197.4 1535.37,1331.97 1867.73,1331.97 1924.05,1388.29 1990.05,1388.29 2056.02,1454.26 2229.19,1454.26 v2(2266.3,1417.16)
  Bottom Layer w6.3: v1(1492.05,717.48) U508.15@1492.05,770.93
NetR62_2: R62.2 U6.32 | length 84.3
  Top Layer w6.3: R62.2@3332.56,618.91 U6.32@3332.56,703.17
NetR63_2: R63.2 R64.1 U2.H2 | length 5412.7
  Top Layer w6.3: v2(2304.32,1590.38) U2.H2@2320.07,1606.13 ; R63.2@2741.35,490.4 2741.78,489.97 R64.1@2801.2,489.97 v1(2801.2,523.72)
  SIGNAL 3 w4.5: v2(2304.32,1590.38) 2234.98,1521.04 2018.51,1521.04 1849.03,1351.56 1030.67,1351.56 636.76,957.65 636.76,861.16 446.04,670.44 446.04,238.94 543.71,141.27 979.73,141.27 1317.79,479.34 1771.46,479.34 1789.83,460.97 2738.45,460.97 v1(2801.2,523.72)
NetR500_1: R500.1 U500.4 U500.5
NetR505_1: R505.1 U500.3 | length 82.8
  Bottom Layer w14: U500.3@3797.13,2151.73 3797.13,2109.7 3807.87,2098.95 R505.1@3833.46,2098.95
NetR513_1: R513.1 R514.2 U3.5 | length 407.6
  Top Layer w6.3: U3.5@3579.11,1744.47 v1(3579.11,1770.53)
  Bottom Layer w6.3: R513.1@3357.94,1955.24 R514.2@3424,1955.24 3424,1928.58 3434.38,1918.2 3487.32,1918.2 3503.78,1901.74 3503.78,1785.16 3518.42,1770.53 v1(3579.11,1770.53)
NetR517_2: R517.2 U504.2 | length 54.6
  Bottom Layer w6.3: R517.2@3792.65,1899.69 3814.88,1899.69 3824.9,1889.67 U504.2@3843.08,1889.67
NetR540_1: R540.1 R541.2 U5.9 | length 235.7
  Top Layer w6.3: U5.9@4204.87,1419.79 4204.87,1448.34 v1(4221.55,1465.02)
  Bottom Layer w6.3: v1(4221.55,1465.02) 4284.23,1465.02 4300.89,1481.68 R540.1@4300.89,1508.87 ; R540.1@4301.12,1508.64 R541.2@4371.24,1508.64
NetR572_1: R572.1 U11.13 U15.4 | length 196.6
  Top Layer w6.3: v1(1193.18,711.4) 1233.33,711.4 U11.13@1233.33,829.5
  Bottom Layer w6.3: v1(1193.18,711.4) R572.1@1193.18,749.74
NetTP5_1: TP5.1 U11.11 | length 207.5
  Top Layer w6.3: TP5.1@1078.22,669.94 1078.22,678.49 1193.96,794.24 U11.11@1193.96,829.5
NetTP7_1: TP7.1 U11.12 | length 342.9
  Top Layer w6.3: TP7.1@1086.46,539.32 1150.24,603.11 1150.24,709.13 1213.64,772.54 U11.12@1213.64,829.5
NetU2_U1: U2.U1 U508.16 | length 1106.4
  Top Layer w6.3: v2(2272.83,1306.92) U2.U1@2288.57,1322.67
  SIGNAL 2 w4.5: v1(1442.05,824.38) 1587.81,970.14 1890.12,970.14 2226.9,1306.92 v2(2272.83,1306.92)
  Bottom Layer w6.3: U508.16@1442.05,770.93 v1(1442.05,824.38)
NetU13_4: U13.4 U14.2 U14.5 U14.10 U14.13 | length 819.9
  Top Layer w6.3: U14.5@2657.68,635.53 U14.10@2889.97,635.53 2945.96,635.53 2961.23,650.8 2961.23,699.95 2948.88,712.3 U14.13@2889.97,712.3 2821.49,712.3 ; U14.2@2657.68,712.3 2821.49,712.3 ; 2809.93,712.3 2821.49,723.86 2833.04,712.3 ; 2813.18,714.79 2829.53,714.79 ; U13.4@2821.49,815.47 2821.49,712.3
OCK_INV: R1.1 R3.2 U501.100 | length 118.5
  Top Layer w15: v5(912.1,2079.54) R3.2@947.73,2079.54 R1.1@947.73,2137.46
  Bottom Layer w10: U501.100@912.1,2054.54 v5(912.1,2079.54)
P1P1V: C1.1 C9.1 C27.1 C35.2 C545.1 C549.1 C550.1 C551.1 C553.1 C556.1 C557.1 C559.1 C560.1 C561.2 C564.1 C566.1 C568.1 C569.1 C570.1 C578.1 C582.1 L512.1 L515.1 L520.2 L522.1 L523.1 R24.2 U2.F9 U2.F11 U2.G6 U2.H13 U2.J6 U2.K13 U2.L6 U2.M13 U2.N6 U2.N8 U2.N9 U2.N11 U6.98 | length 775
  Top Layer w10: v2(2430.31,1590.38) U2.J6@2446.05,1574.64 ; v2(2430.31,1653.38) U2.G6@2446.05,1637.63 ; U2.N6@2446.05,1448.65 v2(2461.8,1432.9) ; U2.L6@2446.05,1511.64 v2(2461.8,1527.39) ; v2(2493.3,1432.9) U2.N8@2509.05,1448.65 ; v2(2524.79,1432.9) U2.N9@2540.54,1448.65 ; U2.F9@2540.54,1669.12 v2(2556.29,1653.38) ; U2.N11@2603.53,1448.65 v2(2619.28,1464.4) ; U2.F11@2603.53,1669.12 v2(2619.28,1653.38) ; v2(2650.78,1558.89) U2.K13@2666.53,1543.14 ; v2(2650.78,1590.38) U2.H13@2666.53,1606.13 ; U2.M13@2666.53,1480.15 v2(2682.27,1464.4)
  Top Layer w11: U6.98@3253.82,1309.47 v4(3253.82,1362)
  Top Layer w15: v1(2014.75,2125.08) 2030.09,2125.08 2046.98,2108.2 C9.1@2046.98,2107.41 ; v1(2206.47,2343.61) 2206.47,2328.26 2223.35,2311.38 C1.1@2224.14,2311.38 ; v1@2894.62,1413.28 2929.68,1413.28 C35.2@2930.06,1413.65
  Bottom Layer w10: v2(2524.79,1432.9) 2543.36,1432.9 2552.78,1423.48 C582.1@2552.78,1398.65
  Bottom Layer w15: v1(2014.75,2125.08) L515.1@2055.2,2125.08 ; L512.1@2206.47,2303.16 v1(2206.47,2343.61) ; v2(2430.31,1653.38) 2430.31,1627.39 C553.1@2435.82,1621.88 C557.1@2435.82,1590.38 ; C551.1@2553.53,1621.88 C549.1@2553.53,1653.38 ; C560.1@2648.02,1558.89 C556.1@2648.02,1590.38
  Bottom Layer w30: L523.1@3018.14,1329.92 3023.14,1334.92 v1(3053.95,1334.92) ; L522.1@3021.1,1491.04 v1(3055.95,1491.04) v1@3056.91,1491.04
  other v1: 2894.25,1412.91 3271.2,1531.85 3221.55,1572.07 3271.34,1572.07 3121.68,1612.34 3171.61,1612.2 3221.55,1612.2 3271.48,1612.2
P1P1V_EN: R16.2 U3.9 U6.1 | length 902.1
  Top Layer w6.3: U6.1@3147.52,1242.54 3109.79,1242.54 3088.37,1263.95 3088.37,1668.98 3105.25,1685.85 3234.51,1685.85 3269.41,1650.96 3389.2,1650.96 3395.83,1657.59 R16.2@3395.83,1679.87 3419.3,1679.87 3424.23,1684.81 U3.9@3468.87,1684.81
P1P8V: C504.1 C505.1 C525.1 C526.1 C541.1 J1.1 J1.2 J1.79 J1.80 L518.2 L521.1 R513.2 U2.E9 U3.4 U6.97 | length 447.9
  Top Layer w9.45: U3.4@3579.11,1724.18 3600.06,1724.18 v1(3617.16,1741.28)
  Top Layer w10: v2(2524.79,1716.37) U2.E9@2540.54,1700.62
  Top Layer w11: v4(3273.51,1265.94) U6.97@3273.51,1309.47
  Top Layer w11.8: J1.79@2488.65,2377.2 2493.23,2381.78 J1.79@2493.23,2393.7 2493.23,2414.08 2489.81,2417.49 ; J1.2@4008.98,2377.16 J1.2@4008.98,2393.7 4008.98,2417.67 ; J1.2@4012.38,2393.7 J1.1@4028.66,2393.7
  Bottom Layer w17: C541.1@2520.63,1716.7 2520.63,1746.45 2536.47,1762.29 2536.47,1802.57 2524.04,1814.99 2524.04,1833.13
  Bottom Layer w20: 2524.04,1833.13 2524.04,1905.78
  Bottom Layer w30: L521.1@3005.84,1626.13 v1(3041.65,1626.13)
  other v1: 3272.71,1721.56 3307.62,1721.56 3272.71,1747.92 3307.62,1747.92 2443.64,2381.73 4052.57,2381.73 2443.64,2411.73 4052.57,2411.73
P1P8V_EN: R13.2 U3.7 U6.2 | length 725.9
  Top Layer w6.3: U6.2@3147.52,1222.85 v4(3192.05,1222.85) ; R13.2@3395.83,1729.87 3409.86,1715.85 v1(3434.66,1715.85) 3442.99,1724.18 U3.7@3468.87,1724.18
  SIGNAL 2 w4.5: v4(3192.05,1222.85) 3192.05,1292.99 3185.33,1299.71 3185.33,1368.69 3324.93,1508.28 3324.93,1606.12 v1(3434.66,1715.85)
P3P3_PG: R534.1 U5.8 | length 387.1
  Top Layer w9.84: U5.8@4224.56,1419.79 4224.56,1433.3 4233.73,1442.47 v1(4249.89,1442.47)
  SIGNAL 2 w20: v1(4121.89,1589.15) 4142.79,1610.05 4237.51,1610.05 4262.53,1585.03 4262.53,1455.11 v1(4249.89,1442.47)
  Bottom Layer w20: v1(4121.89,1589.15) 4121.89,1612.81 R534.1@4131.33,1622.25
P3P3_PG6: R20.1 R534.2 U504.5 | length 463
  Top Layer w30: R20.1@4178.58,1625.67 v1(4178.58,1652.08)
  SIGNAL 4 w30: v1(3946.71,1889.67) 4025.77,1889.67 4104.02,1811.41 4104.02,1726.64 v1(4178.58,1652.08)
  Bottom Layer w6.3: R534.2@4178.58,1622.25 v1(4178.58,1652.08)
  Bottom Layer w12: U504.5@3919.86,1889.67 v1(3946.71,1889.67)
P3P3V: C3.1 C30.1 C33.1 C40.1 C44.1 C59.1 C528.1 C547.1 C552.1 C555.1 C558.1 C562.1 C563.1 C567.1 C574.1 C579.1 C581.1 C595.1 C598.1 C599.1 C606.2 C608.1 C614.1 J1.43 L1.1 L3.1 L4.1 L514.1 L519.1 L524.2 R1.2 R2.2 R9.2 R42.2 R43.2 R44.2 R45.2 R58.2 R59.2 R501.2 R502.2 R503.2 R524.2 R553.2 R554.1 R557.2 R558.1 R561.2 R570.2 R571.2 R580.1 R592.2 R593.2 SW1.2 SW2.2 SW3.2 SW4.2 U1.6 U2.F14 U2.G5 U2.G14 U2.H5 U2.H14 U2.J14 U2.K6 U2.L5 U2.L14 U2.M6 U2.M14 U2.N5 U2.N7 U2.P5 U2.P8 U6.96 U7.3 U9.5 U10.5 U12.15 U13.5 U14.14 U15.5 U508.2 U510.2 U510.5 | length 2729.7
  Top Layer w10: v2(2398.81,1401.41) U2.P5@2414.56,1417.16 ; v2(2398.81,1432.9) U2.N5@2414.56,1448.65 ; v2(2398.81,1495.9) U2.L5@2414.56,1511.64 ; v2(2398.81,1621.88) U2.H5@2414.56,1606.13 ; v2(2398.81,1653.38) U2.G5@2414.56,1637.63 ; v2(2430.31,1464.4) U2.M6@2446.05,1480.15 ; v2(2430.31,1527.39) U2.K6@2446.05,1543.14 ; v2(2461.8,1464.4) U2.N7@2477.55,1448.65 ; v2(2493.3,1401.41) U2.P8@2509.05,1417.16 ; U2.M14@2698.02,1480.15 v2(2713.77,1464.4) ; U2.L14@2698.02,1511.64 v2(2713.77,1527.39) ; U2.J14@2698.02,1574.64 v2(2713.77,1590.38) ; U2.H14@2698.02,1606.13 v2(2713.77,1621.88) ; U2.G14@2698.02,1637.63 v2(2713.77,1653.38) ; U2.F14@2698.02,1669.12 v2(2713.77,1684.87)
  Top Layer w11: U7.3@1288.48,1200.22 1316.06,1200.25 1329.15,1213.34 C40.1@1348.1,1213.34 v1(1377.91,1213.34) ; J1.43@3201.89,2393.7 3201.89,2356.66 v1(3211.14,2347.41) ; U6.96@3293.19,1309.47 v4(3293.19,1361.99)
  Top Layer w15.5: U13.5@2821.49,866.65 v1(2854.22,866.65)
  Top Layer w17: v1(553.64,828.47) U12.15@612.78,828.47 ; U14.14@2889.97,737.89 v1(2933.56,737.89)
  Top Layer w20: C44.1@1492.05,1133.14 v1(1492.05,1186.58) ; SW2.2@2108.66,812.38 2119.24,801.8 v1(2159.49,801.8)
  Top Layer w23: R2.2@593.75,2121.87 v1(593.75,2157.61) ; v5(912.98,2184.7) R1.2@947.73,2184.7 C3.1@947.73,2243.36 v5(982.48,2243.36) ; v1(1196.48,635.93) U15.5@1235.17,635.93 ; v1(1404.06,770.93) R59.2@1444.81,770.93 ; v1(1442.05,1051.14) R44.2@1442.05,1085.89 ; v1(1542.05,1051.14) R45.2@1542.05,1085.89 ; v1(1742.05,1051.14) R42.2@1742.05,1085.89 ; v1(1792.05,1051.14) R43.2@1792.05,1085.89
  Top Layer w25: v1(2731.86,916.15) U9.5@2731.86,954.84 ; U10.5@2820.94,1063.11 2820.94,1096.46 2830.07,1105.58 2830.07,1106.26 2852.03,1128.22 2852.71,1128.22 v1(2854.03,1129.55)
  Top Layer w26: v1(960.15,1457.07) 998.31,1457.07 L3.1@1009.59,1445.8
  Top Layer w27: v1(1924.78,768.98) SW1.2@1924.78,812.38 ; v1(2292.55,769.19) SW3.2@2292.55,812.38 ; v1(2476.09,757.55) SW4.2@2476.09,811.2
  Top Layer w30: v1(874.3,1432.66) C33.1@908.92,1432.66 ; R58.2@1744.81,774.69 v1(1744.82,832.07)
  Top Layer w40: L1.1@741.96,1808.67 v1(741.96,1851.67)
  Bottom Layer w20: v1(1931.24,929.27) C598.1@1966.45,929.27 U510.2@2026.36,929.27
  Bottom Layer w23: v1(553.64,828.47) C606.2@612.78,828.47 ; v1(738.81,259.94) R593.2@773.86,259.94 ; R592.2@951.3,259.94 v1(986.35,259.94) ; R503.2@1019.46,2251.97 v1(1019.46,2287.72) ; R502.2@1070.46,2251.97 v1(1070.46,2287.72) ; R501.2@1121.46,2251.97 v1(1121.46,2287.72) ; v1(1196.48,635.93) C614.1@1235.17,635.93 ; U508.2@1492.05,1133.14 v1(1492.05,1186.58) ; v1(1733.91,326.72) R580.1@1733.91,361.77 ; R571.2@2108.81,825.77 2135.52,825.77 v1(2159.49,801.8) ; U510.5@2134.62,891.87 v1(2173.34,891.87) ; R553.2@2413.39,1131.21 R554.1@2467.61,1131.21 ; v1(2467.76,1095.86) R554.1@2467.76,1131.06 ; v1(2530.07,1095.86) R558.1@2530.07,1131.06 ; v1(2592.39,1095.86) R557.2@2592.39,1131.06 ; L524.2@2819.89,1129.17 L524.2@2820.94,1129.17 ; C595.1@2820.94,1063.11 L524.2@2820.94,1129.17 ; L524.2@2820.94,1130.22 L524.2@2820.94,1129.17 ; v1@2853.65,1129.17 L524.2@2820.94,1129.17 ; C608.1@2889.97,737.89 v1(2933.56,737.89) ; v1@2973.19,1046.73 R561.2@3015.49,1046.73
  Bottom Layer w30: C528.1@741.96,1807.68 v1(741.96,1851.67)
  Bottom Layer w31: C599.1@2731.86,950.9 v1(2731.86,916.15) 2741.6,906.41 C59.1@2741.6,867.52 R570.2@2741.6,815.77
  Bottom Layer w40: L519.1@3006.38,1688.62 v1(3041.65,1688.62)
  other v1: 2973.19,1046.87 1462.49,1426.3 1462.49,1459.27 3534.07,1812.17 3572.98,1812.17 3609.39,1812.17 770.71,2161.25 805.71,2161.25
P3P3V_EN: R5.2 R46.2 U1.3 U6.3 | length 3103.6
  Top Layer w6.3: v1(1592.05,1051.14) R46.2@1592.05,1085.89 ; v4(3103,1203.17) U6.3@3147.52,1203.17 ; U1.3@3685.07,1917.19 R5.2@3685.07,1985.18 v1(3722.76,1985.18)
  SIGNAL 1 w4.5: v1(1592.05,1051.14) 1623.79,1082.89 1873.25,1082.89 1972.87,983.27 2867.75,983.27 2964.91,1080.43 3010.19,1080.43 3074.5,1144.74 3074.5,1174.68 v4(3103,1203.17)
  SIGNAL 2 w4.5: v4(3103,1203.17) 3103,1567.82 3086.35,1584.47 3086.35,1676.83 3261.28,1851.76 3589.34,1851.76 v1(3722.76,1985.18)
P3P3V_REG: C17.1 C18.1 C19.1 C26.2 C42.1 C51.2 C535.1 C536.1 C537.1 C593.1 C596.1 C597.1 D2.1 D4.2 L2.2 L516.1 R14.2 R20.2 R31.2 R48.2 R49.2 R60.2 R516.1 R524.1 R535.2 R560.2 R572.2 U1.1 U3.3 U4.5 U7.7 U8.5 U11.1 U11.23 U12.16 U504.6 | length 1118.9
  Top Layer w9: v1(1092.55,1007.83) 1109.35,991.03 U11.1@1130.85,991.03
  Top Layer w9.42: U11.23@1316.13,971.35 v1(1350.53,971.35)
  Top Layer w9.45: U3.3@3579.11,1704.49 3613.88,1704.49 ; 3614.67,1704.44 R14.2@3623.86,1695.25 ; 3615.63,1704.15 3625.84,1714.36 3639.71,1714.36
  Top Layer w11.8: C42.1@1103.81,1166 1118.35,1180.54 U7.7@1162.49,1180.54
  Top Layer w15.5: U4.5@389.46,1452.14 v1(429.69,1452.14)
  Top Layer w20: v1(1194.11,1074.34) R48.2@1194.11,1104.45 ; v1(1256.86,1074.34) R49.2@1256.86,1104.45 ; v1(1350.53,971.35) v1(1382.38,971.35)
  Top Layer w23: v1(429.69,1452.14) R31.2@469.93,1452.12
  Top Layer w23.6: v1(579.03,746.73) C51.2@612.78,746.73 ; v1(764.07,746.73) R60.2@797.82,746.73 v1(797.82,712.98) ; v1(892.65,1025.72) U8.5@932.17,1025.72 ; L2.2@3969.98,1599.88 4043.54,1599.88 4065.93,1622.27 R20.2@4131.33,1622.27
  Top Layer w25: v1@1104.17,1136.26 C42.1@1104.17,1164.78
  Top Layer w30: v1(612.78,716.92) C51.2@612.78,746.73 U12.16@612.78,796.43 ; D2.1@701.79,1553.12 v1(743.44,1553.12) ; D4.2@715.6,1351.12 v1(755.25,1351.12)
  Bottom Layer w23: v1(1092.55,1007.83) 1114.06,1007.82 C597.1@1130.85,991.03
  Bottom Layer w23.5: v1(1107.51,749.74) R572.2@1145.94,749.74
  Bottom Layer w30: v1(892.65,1025.72) C593.1@932.17,1025.72 955.79,1025.72 R560.2@989.78,1059.71
  Bottom Layer w31.5: C596.1@1320.21,971.35 v1(1350.53,971.35)
  other v1: 1104.54,1135.89 3778,1633.42 3836.66,1633.42 3889.65,1663.65 3961.34,1663.65 4033.02,1663.65 3892.37,1798.19 3964.06,1798.19 4035.74,1798.19 3809.8,1813.82 3722.76,1840.3
P3P3V_TPS99K: C47.1 C52.1 C516.1 C609.1 C612.2 L7.1 R500.2 R516.2 R585.2 R590.2 U6.14 U6.26 U6.36 | length 389.7
  Top Layer w11: v4(3103,986.63) U6.14@3147.52,986.63 ; v4(3411.3,658.64) U6.36@3411.3,703.17
  Top Layer w20: C47.1@3062.87,986.63 v4(3103,986.63) ; v4(3189.93,703.17) U6.26@3210,703.17 ; C52.1@3411.3,618.91 v4(3411.3,658.64) ; L7.1@4063.07,860.4 v1(4101.72,860.4)
  Bottom Layer w23: C612.2@3156.54,644.59 C609.1@3156.54,703.17 v4(3189.93,703.17) ; R590.2@3778.03,308.15 v1(3813.08,308.15) ; v1(4237.09,365.19) R585.2@4272.15,365.19
  other v1: 3649.74,2019.69
P6P5V: C2.1 C50.1 C55.1 C512.1 C513.1 C565.1 C590.1 C592.1 C604.1 C615.1 D1.1 FB500.1 R505.2 R508.2 U6.42 U6.55 U6.65 U6.67 U6.79 U500.1 U500.6 | length 669.8
  Top Layer w10.5: U6.55@3753.82,848.34 C50.1@3847.81,848.34
  Top Layer w11: 3529.41,658.64 U6.42@3529.41,703.17 ; v4(3627.84,1264.94) U6.79@3627.84,1309.47 ; v4(3709.3,848.84) U6.55@3753.82,848.84 ; v4(3709.3,1045.69) U6.65@3753.82,1045.69 ; v4(3709.3,1085.06) U6.67@3753.82,1085.06 ; C50.1@3847.81,848.84 C50.1@3849.78,848.84
  Top Layer w23.62: C55.1@3518.58,601.39 3518.58,618.15 3529.41,628.98 3529.41,658.64
  Bottom Layer w15: v1(3847.81,798.72) C604.1@3847.81,848.22
  Bottom Layer w19: v1(1209.42,2295.76) FB500.1@1237.32,2295.76 ; v1(1237.32,2267.86) FB500.1@1237.32,2295.76 ; v1(1265.22,2295.76) FB500.1@1237.32,2295.76
  Bottom Layer w30: v4(3627.84,1264.94) 3627.84,1321.67 3645.48,1339.31 C565.1@3645.48,1413.87
  other v1: 3929.67,2100.08 3974.79,2111.14 3929.67,2148.66 3942.91,2228.18 4000.48,2228.18 3942.91,2275.15
  other v4: 3472.25,584.91 3472.73,612.94
P6P5V_F: C506.1 FB500.2 J2.5 | length 137
  Top Layer w15: v1(1237.32,2362.1) J2.5@1237.32,2411.61
  Bottom Layer w19: FB500.2@1237.32,2333.08 v1(1237.32,2362.1) 1237.32,2389.89 C506.1@1259.04,2411.61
